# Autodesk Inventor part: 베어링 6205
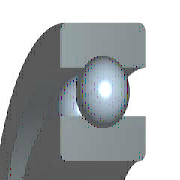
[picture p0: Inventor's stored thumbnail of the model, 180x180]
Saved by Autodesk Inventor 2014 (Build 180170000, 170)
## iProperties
Created: 2012-02
Part Number: 베어링 6205
Material: 강철, 연강
Description: 깊은 그루브 볼 베어링
Document SubType Name: Modeling
Standard: KS B 2023
Designer: mduedu
Standards Organization: KS
Language: ko-KR
Size Designation: 6205 - 25 x 52 x 15
Categories: <MemberInstance><Categories><Category DisplayName="샤프트 부품" InternalName="7f7aeb1f-a693-4053-b835-cee3144e0d98" Mnemonic="SHFT"><Category DisplayName="베어링" Inter
Density: 1 g/cm^3
Appearance: 노란색
IsCustomPart: 1
Author: mduedu
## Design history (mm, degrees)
sketch "스케치" dims "d0" = 7.02 (= -0.26 x WD + 0.26 x BD)
  geometry: L1 (3.99, 19.25)-(11.01, 19.25); L2 (7.5, 19.25)-(7.5, 15.74); L3 (7.5, 19.25)-(7.5, 22.76); L4 (4.892, 16.901)-(0, 16.901); L5 (0, 12.5)-(15, 12.5); L6 (4.892, 21.599)-(0, 21.599); L7 (0, 26)-(15, 26); L8 (15, 12.5)-(15, 16.901); L9 (10.108, 16.901)-(15, 16.901); L10 (10.108, 21.599)-(15, 21.599); L11 (15, 26)-(15, 21.599); L12 (-1.4, 0)-(8.4, 0) reference; L13 (0, -0.3)-(0, 5.3) reference
  constraints: 22 end point, 4 point on line, 2 collinear, 2 perpendicular, 2 symmetric about line, 1 midpoint, 1 parallel, 14 other
  dimensions: "d9" = 25 diameter of L5 L12 (= WD); "d11" = 52 diameter of L7 L12 (= BD); "d12" = 15 distance between parallel lines of L8 L13 (= KB); "d13" = 33.802 diameter of L9 L12 (= 0.326 x BD + 0.674 x WD)
revolve "본체" stored, may be unused: angle "d6" = 90 deg
revolve "볼" stored, may be unused: angle "d7" = 90 deg
pattern_circular "IDS_ARRAYBALL[SIMPL:T]" dims angle "d3" = 360 deg
body "Solid1"
fillet "모깎기1" dims "d1" = 1 (= KRS)
other parameters: "WD" = 25 [user parameter; used in 5 equation terms], "BD" = 52 [user parameter; used in 5 equation terms], "KB" = 15 [user parameter; used in 1 equation term], "KRS" = 1 [user parameter; used in 1 equation term], "d4" = 0, "d5" = 0, "d8" = 0, "d14" = 0, "d15" = 0, "BBA" = 0 [user parameter], "BC0" = 7800000 [user parameter], "BC" = 1.4e+07 [user parameter], "BR" = 26 (= 0.5 x BD) [user parameter], "WR" = 12.5 (= 0.5 x WD) [user parameter]
